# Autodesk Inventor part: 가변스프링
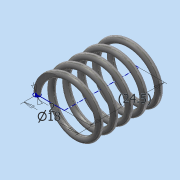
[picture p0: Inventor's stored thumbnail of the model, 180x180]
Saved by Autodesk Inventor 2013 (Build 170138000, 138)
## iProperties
Created: 2018-12
Part Number: 가변스프링
Material: 스테인리스강
Document SubType Name: Modeling
Designer: dgall
Density: 1 g/cm^3
Mass: 0.870362 g
Surface Area: 17.7141 cm^2
Volume: 0.870362 cm^3
Author: dgall
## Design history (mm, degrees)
sketch "스케치1"
  geometry: L1 (0, 0)-(0, 24.5); L2 (0, 24.5)-(-9, 24.5); L3 (0, 0)-(-9, 0); C1 r 1 at (-9, 0)
  constraints: 6 end point, 1 centre point, 1 coincident, 1 parallel, 1 perpendicular, 1 vertical, 1 vertical alignment
  dimensions: "d0" = 24.49999 distance of L1.start L1.end (derived); "d1" = 18 diameter of L3.end L1; "d2" = 2 diameter of C1
feature "코일1" pitch "d3" = 10; turns "d5" = 5; dims "d4" = 24.49999 (= d0), "d6" = 0, angle "d7" = 90 deg, angle "d8" = 90 deg, "d9" = 0, "d10" = 0
node "작업 평면1"
feature "분할1"
feature "분할2"
node "솔리드1"
other parameters: "d11" = 0
